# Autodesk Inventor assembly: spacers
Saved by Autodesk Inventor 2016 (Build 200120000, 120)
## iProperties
Created: 2018-05
Part Number: spacers
Document SubType Name: Assembly
Designer: Administrator
Title: spacers
Author: Administrator
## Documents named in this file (2)
- c:\worker\convert-fusion-mar-2018\tmp\job-1\16\output\files\8c58ff39-88bb-4352-afd9-60265520bae5\spacers.iam
- c:\worker\convert-fusion-mar-2018\tmp\job-1\16\output\files\8c58ff39-88bb-4352-afd9-60265520bae5\Component67.ipt
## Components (1 placed, 1 different names)
1. Component67:1
